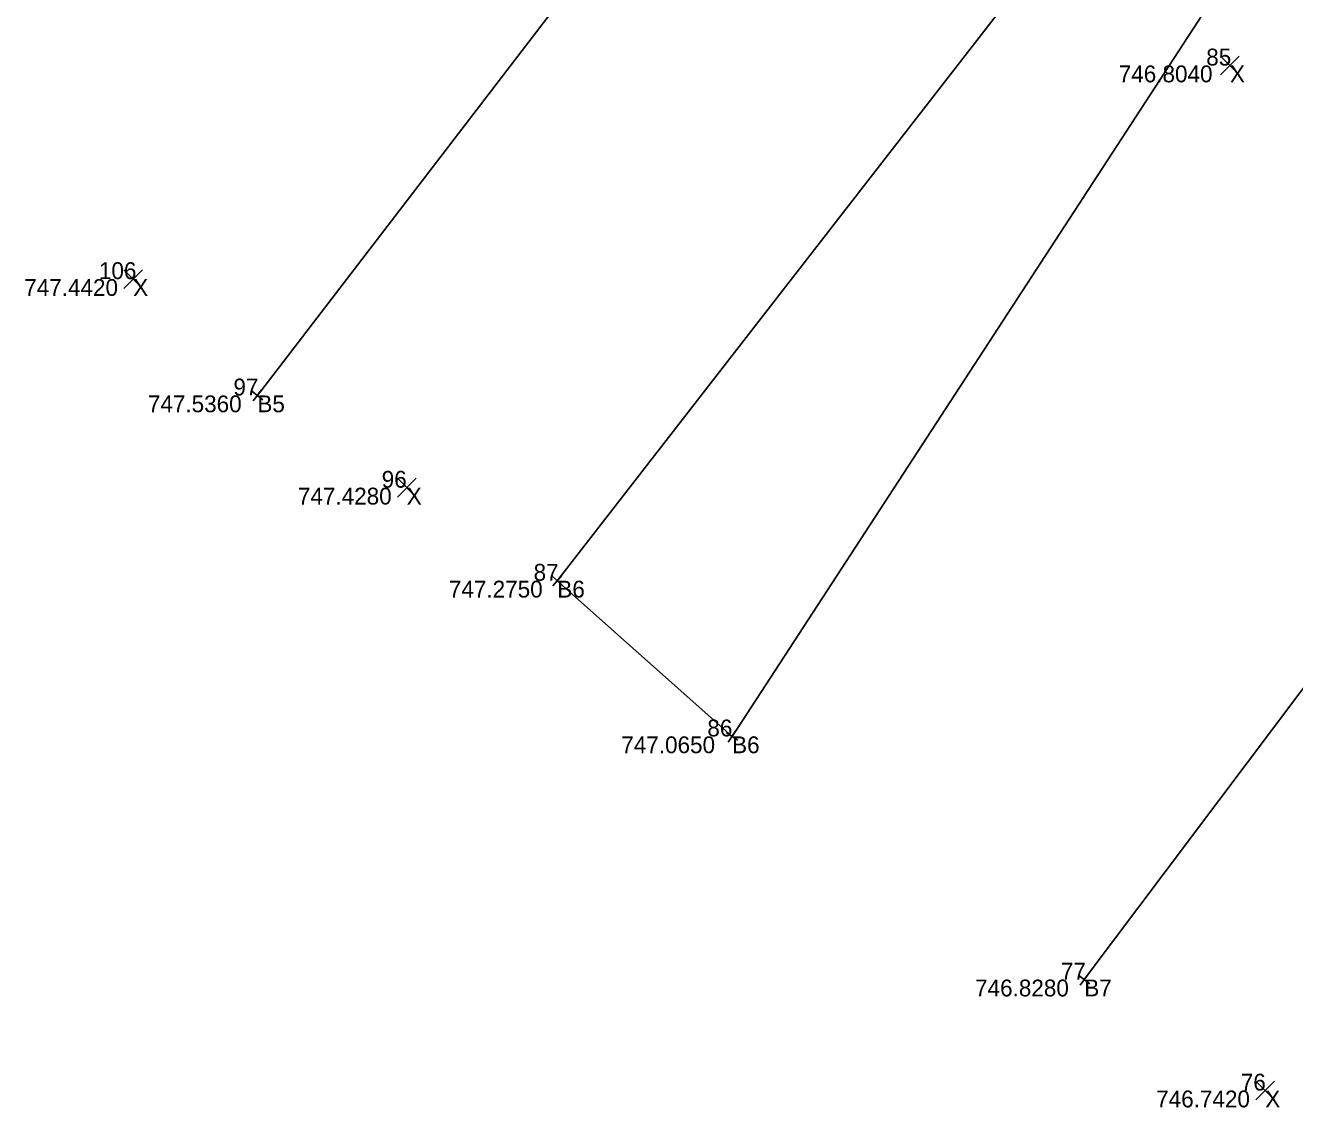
# Model space of a CAD drawing. Extents: x 1857337 to 1857837, y 693958 to 694371.
# Drawn here: x 1857678.08 to 1857723.38, y 694162.88 to 694201.48 of the extents above; entities that cross this region are included whole.
import ezdxf

# ---------------------------------------------------------------- set-up
doc = ezdxf.new("R2010")
doc.units = 0
for name, color, linetype in [('BR_X_SV_Pier_Cap_Bottom', 7, 'Continuous'), ('SV_X_Text_Comment', 7, 'Continuous'), ('SV_X_Text_Description', 7, 'Continuous'), ('SV_X_Text_Elevation', 7, 'Continuous'), ('SV_X_Text_Name', 7, 'Continuous'), ('UT_X_Electric_Cells', 7, 'Continuous')]:
    doc.layers.add(name, color=color, linetype=linetype)

msp = doc.modelspace()

# ---------------------------------------------------------------- linework, layer by layer
at = {"layer": 'BR_X_SV_Pier_Cap_Bottom'}
for p, q in [((1857686.56, 694188.133), (1857686.164, 694188.437)), ((1857686.514, 694188.483), (1857686.21, 694188.087)), ((1857686.362, 694188.285), (1857686.362, 694188.285)), ((1857697.253, 694181.51), (1857696.879, 694181.842)), ((1857696.9, 694181.489), (1857697.232, 694181.863)), ((1857697.066, 694181.676), (1857697.066, 694181.676)), ((1857703.44, 694176.332), (1857703.166, 694175.914)), ((1857703.512, 694175.987), (1857703.094, 694176.26)), ((1857703.303, 694176.123), (1857703.303, 694176.123)), ((1857716.071, 694167.298), (1857715.671, 694167.598)), ((1857716.021, 694167.648), (1857715.721, 694167.248)), ((1857715.871, 694167.448), (1857715.871, 694167.448))]:
    msp.add_line(p, q, dxfattribs=at)
at = {"layer": 'SV_X_Text_Elevation'}
for p, q in [((1857720.736, 694199.72), (1857721.402, 694200.388)), ((1857720.736, 694200.388), (1857721.402, 694199.72)), ((1857681.597, 694192.101), (1857682.263, 694192.769)), ((1857681.597, 694192.769), (1857682.263, 694192.101)), ((1857691.359, 694184.66), (1857692.025, 694185.328)), ((1857691.359, 694185.328), (1857692.025, 694184.66)), ((1857721.997, 694163.156), (1857722.663, 694163.824)), ((1857721.997, 694163.824), (1857722.663, 694163.156))]:
    msp.add_line(p, q, dxfattribs=at)
at = {"layer": 'UT_X_Electric_Cells'}
for points in [[(1857781.428, 694311.93), (1857762.198, 694286.329), (1857747.53, 694267.733), (1857737.362, 694255.214), (1857727.429, 694241.82), (1857719.125, 694230.499), (1857704.829, 694212.344), (1857686.362, 694188.285)], [(1857789.956, 694304.598), (1857771.692, 694278.296), (1857757.221, 694258.854), (1857703.303, 694176.123), (1857697.066, 694181.676), (1857715.676, 694205.645), (1857728.737, 694223.567), (1857737.207, 694233.914), (1857746.662, 694246.317)], [(1857810.28, 694291.033), (1857789.924, 694262.397), (1857775.396, 694247.353), (1857765.086, 694232.211), (1857755.635, 694219.954), (1857747.975, 694210.111), (1857734.181, 694191.788), (1857715.871, 694167.448)]]:
    msp.add_lwpolyline(points, dxfattribs=at)

# ---------------------------------------------------------------- texts
at = {"layer": 'SV_X_Text_Comment'}
for s, p in [('X', (1857721.069, 694199.454)), ('X', (1857681.93, 694191.835)), ('B5', (1857686.362, 694187.685)), ('X', (1857691.692, 694184.394)), ('B6', (1857697.066, 694181.076)), ('B6', (1857703.303, 694175.523)), ('B7', (1857715.871, 694166.848)), ('X', (1857722.33, 694162.89))]:
    msp.add_text(s, height=0.6, dxfattribs=at).set_placement(p)
at = {"layer": 'SV_X_Text_Description'}
for s, p in [('746.8040', (1857717.101, 694199.454)), ('747.4420', (1857678.042, 694191.835)), ('747.5360', (1857682.455, 694187.685)), ('747.4280', (1857687.809, 694184.394)), ('747.2750', (1857693.197, 694181.076)), ('747.0650', (1857699.349, 694175.523)), ('746.8280', (1857711.974, 694166.848)), ('746.7420', (1857718.437, 694162.89))]:
    msp.add_text(s, height=0.6, dxfattribs=at).set_placement(p)
at = {"layer": 'SV_X_Text_Name'}
for s, p in [('85', (1857720.223, 694200.054)), ('106', (1857680.707, 694192.435)), ('97', (1857685.507, 694188.285)), ('96', (1857690.799, 694184.994)), ('87', (1857696.22, 694181.676)), ('86', (1857702.42, 694176.123)), ('77', (1857715.035, 694167.448)), ('76', (1857721.456, 694163.49))]:
    msp.add_text(s, height=0.6, dxfattribs=at).set_placement(p)

doc.saveas('drawing.dxf')
